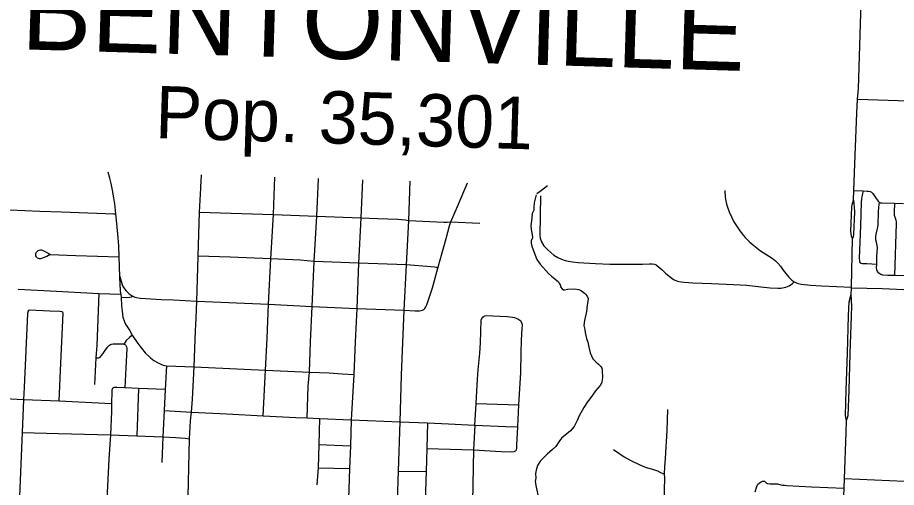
# Model space of a CAD drawing. Extents: x 653372 to 905732, y 627442 to 787275.
# Drawn here: x 659009 to 666097, y 749842 to 753633 of the extents above; entities that cross this region are included whole.
import ezdxf

# ---------------------------------------------------------------- set-up
doc = ezdxf.new("R2010")
doc.units = 0
for name, color, linetype in [('33', 7, 'Continuous'), ('34', 7, 'Continuous'), ('35', 7, 'Continuous'), ('6', 7, 'Continuous')]:
    doc.layers.add(name, color=color, linetype=linetype)

msp = doc.modelspace()

# ---------------------------------------------------------------- linework, layer by layer
at = {"layer": '33'}
for points in [[(665750.6, 752158.5), (665753.4, 752237.5), (665765.4, 752523.4), (665776.4, 752861.8), (665784.2, 752975.8), (665790.1, 753059), (665809.2, 753667.6), (665821.4, 753986.1), (665822.6, 754011), (665827.6, 754110), (665837.6, 754326.1), (665845.5, 754476.3), (665857.3, 754725.5), (665870.8, 755060.3), (665875.3, 755151.5), (665889.4, 755308.4), (665902.2, 755504.9), (665923, 756054.4), (665953, 756658.5), (665962.3, 756805.9), (665967.2, 756905.6), (665969, 756942), (665972.3, 757010.8)], [(665784.2, 752975.8), (666604.8, 752948.1)], [(659841.5, 751402.3), (659836.4, 751474.9), (659832.3, 751543), (659828.2, 751703.3), (659824.2, 751792.6), (659819.4, 751855.2), (659808.5, 751972.8), (659800.2, 752050.5), (659792, 752130.5), (659785.1, 752178.6), (659774.7, 752240.2), (659764.1, 752294), (659753.7, 752337.3), (659739.1, 752385.9)], [(660433.3, 750816.3), (660438.3, 750963.7), (660443.8, 751105.4), (660448.1, 751206.8), (660453.3, 751345.4), (660460, 751521.8), (660464.4, 751708.4), (660475.1, 752063.9), (660485.8, 752257.1), (660489.6, 752322.7), (660491.2, 752351.6), (660491, 752363.3)], [(660989.1, 750420.2), (661008.7, 750787.3), (661021.1, 751046.1), (661033.3, 751320.2), (661051.6, 751686.4), (661071.6, 752044.4), (661084.3, 752345.5)], [(661344.1, 750402.3), (661352.6, 750659.3), (661362.5, 750773.2), (661370.6, 751016.3), (661385.3, 751301.8), (661402.2, 751666.1), (661422.1, 752029.5), (661435.4, 752330.7), (661435.6, 752334.9)], [(661791.6, 752324.2), (661776.9, 752016.2)], [(662051.6, 749054.1), (662057.6, 749373.6), (662064.6, 749504.9), (662070.7, 749595.4), (662074.8, 749814.9), (662080.9, 749974.3), (662093.6, 750371.3), (662106.3, 750747.6), (662116.4, 751010.5), (662127.9, 751272.1), (662145.5, 751637.9), (662164.3, 751997), (662174.6, 752312.7)], [(662127.9, 751272.1), (662214.3, 751267.1), (662249.8, 751267), (662264.2, 751269), (662274.2, 751272.2), (662285.2, 751278.8), (662292.8, 751286.9), (662301.6, 751299), (662310.5, 751315.5), (662354.5, 751451.8), (662397.3, 751612.4), (662464.6, 751849.6), (662492.8, 751953.8), (662503, 751984.3), (662557.6, 752107.5), (662637.6, 752298.8)], [(665753.4, 752237.5), (665828.4, 752234.1), (665861.3, 752233.1), (665870.8, 752231.7), (665884.7, 752228.5), (665896.8, 752223.1), (665907.7, 752213.8), (665933.9, 752174.4), (665949.4, 752150.5), (665959.2, 752141.8), (665965.3, 752138.8), (665979.2, 752137.9), (666080.9, 752135.4), (666154, 752133.2)], [(665828.4, 752234.1), (665822.1, 752212.5), (665816.9, 752188), (665815.2, 752171.3), (665813.8, 752141.2), (665807.1, 751956.3), (665797.4, 751689.7), (665798.1, 751674), (665799.4, 751661.7), (665804.2, 751654.2), (665810.2, 751650.7), (665820.2, 751648.7), (665859.3, 751647.6), (665938, 751644.3)], [(658461, 752105.2), (658630.8, 752096.9), (658719, 752093), (658946, 752082.2), (659187.6, 752071.7), (659363.4, 752065.7), (659718.3, 752051.8), (659781.9, 752049.9), (659800.2, 752050.5)], [(665742.6, 751851.8), (665735.5, 751869.4), (665731.1, 751894.4), (665730.1, 751906.1), (665737, 752105.6), (665740.1, 752122.7), (665750.6, 752158.5)], [(665750.6, 752158.5), (665753.2, 752130.6), (665756.7, 752103.8), (665759, 752066.8), (665751.7, 751882.2), (665748.1, 751862.6), (665742.6, 751851.8)], [(666223.1, 751548.5), (666081.2, 751551.6), (666028.1, 751552.7), (665986.8, 751554.5), (665971.3, 751559.4), (665954.3, 751570), (665944.1, 751585.4), (665938.3, 751597.9), (665936, 751613), (665938, 751644.3), (665939.9, 751706.3), (665943.7, 751776.1), (665941.5, 751795.1), (665935.5, 751821), (665930.5, 751840.8), (665929.9, 751857), (665930.9, 751870.2), (665936.7, 751895.8), (665942.4, 751920.8), (665948.1, 751941.3), (665948.7, 751960.9), (665952.3, 752063.4), (665954.1, 752104.1), (665957.5, 752124.7), (665959.2, 752141.8)], [(666080.9, 752135.4), (666078.6, 752062.4), (666079.6, 752039.4), (666085.7, 752018), (666092.9, 751997.1), (666094.8, 751986.4), (666094.9, 751971.3), (666081.2, 751551.6)], [(660475.1, 752063.9), (661071.6, 752044.4), (661422.1, 752029.5), (661776.9, 752016.2), (661914.8, 752011.3), (662074.9, 752005.5), (662135.7, 752000.7), (662164.3, 751997), (662446.2, 751983), (662474.8, 751983.6), (662503, 751984.3), (662736.4, 751973.4)], [(661776.9, 752016.2), (661759, 751650.4), (661744.7, 751285.7), (661731.1, 751017.8), (661719.8, 750752.1), (661699.9, 750386.5), (661692.7, 750178.4), (661685.1, 749994.1), (661674.2, 749669.3)], [(665731.4, 751401.5), (665733.8, 751450.4), (665733.9, 751459), (665742.6, 751851.8)], [(659272.1, 751721.8), (659243.7, 751705.7), (659208.2, 751691.5), (659195.1, 751687.7), (659185.5, 751687.4), (659177.7, 751689.3), (659170.9, 751692), (659163.9, 751696.8), (659160.5, 751701.7), (659156.2, 751711.6), (659154.9, 751722.1), (659156.8, 751730.1), (659159.9, 751736.8), (659166.7, 751746.4), (659175.7, 751752.6), (659183.6, 751756.3), (659193, 751758.3), (659202.1, 751757.7), (659213.4, 751754.4), (659227.2, 751748.1), (659246, 751736.9), (659259.7, 751728.7), (659272.1, 751721.8)], [(659272.1, 751721.8), (659477.8, 751714.3), (659828.2, 751703.3)], [(662397.3, 751612.4), (662386.6, 751615.7), (662372.9, 751619.1), (662341.9, 751622.5), (662145.5, 751637.9), (661759, 751650.4), (661402.2, 751666.1), (661288.2, 751675.3), (661051.6, 751686.4), (660722.2, 751700.7), (660464.4, 751708.4)], [(659832.3, 751543), (659856.2, 751468.8), (659870.6, 751444.9), (659885.1, 751427), (659908.5, 751405.2), (659925.6, 751393.2), (659937.9, 751385.4), (659953.5, 751377.3), (659969, 751373.2), (659998.4, 751369.3), (660043.5, 751366.8), (660166.1, 751359.5), (660265.9, 751354.3), (660453.3, 751345.4), (661033.3, 751320.2), (661385.3, 751301.8), (661744.7, 751285.7), (662127.9, 751272.1)], [(665271.4, 751501.3), (665303.3, 751487), (665327.7, 751480.7), (665404.2, 751474.5), (665491.4, 751469.6), (665733.9, 751459)], [(659013, 751440.7), (659321.8, 751425.9), (659664.6, 751405.6), (659841.5, 751402.3)], [(659664.6, 751405.6), (659647.7, 750990.7), (659640.1, 750887.6), (659629.7, 750671.7)], [(659841.5, 751402.3), (659843.5, 751376), (659846.6, 751306.6), (659852, 751263.6), (659858.9, 751217.1), (659871.1, 751178.3), (659879.5, 751158.5), (659889.1, 751144.3), (659910.4, 751111.7), (659932.5, 751069.2), (659980.1, 751003.7), (660039.1, 750927.8), (660081.4, 750888.6), (660107, 750867.2), (660136.5, 750849.6), (660163.4, 750836), (660183.4, 750827.2), (660209.6, 750822.5), (660433.3, 750816.3), (661008.7, 750787.3), (661362.5, 750773.2), (661522.5, 750765.9), (661625.9, 750759.2), (661719.8, 750752.1)], [(665693.7, 750381), (665684.9, 750422.8), (665691.6, 750627.8), (665701.1, 750924.5), (665710.2, 751227.8), (665715.4, 751339.6), (665731.4, 751401.5)], [(665693.7, 750381), (665708, 750422), (665714.7, 750627.1), (665724.2, 750923.8), (665733.3, 751226.9), (665736.7, 751301.4), (665731.4, 751401.5)], [(666214.6, 751433.7), (665983, 751445.1), (665733.8, 751450.4)], [(659843.5, 751376), (659886.9, 751375.3), (659914.2, 751376.1), (659926.4, 751380), (659937.9, 751385.4)], [(659345.2, 750540.6), (659357.7, 750843.4), (659376.7, 751246.8), (659373.6, 751254.2), (659365.4, 751258.9), (659348.5, 751260.6), (659268.9, 751265.2), (659105, 751271.2), (659096, 751268.7), (659091.8, 751260.4), (659091, 751252.1), (659089.7, 751244.4), (659061.2, 750649.5), (659057.7, 750550.3), (659046.7, 750285), (659021.8, 749707.4)], [(662310.1, 750155.8), (662687, 750145.5), (662909.8, 750133.2), (662990.1, 750130.2), (663015.1, 750131.9), (663025.3, 750138.5), (663033, 750146.4), (663034.5, 750155.7), (663036, 750183.7), (663042.2, 750330.8), (663052.5, 750507.3), (663067.9, 750769.7), (663069.5, 750927.6), (663073.2, 751030.4), (663079.2, 751123.7), (663081.2, 751151.1), (663077.9, 751164.9), (663068.9, 751182.8), (663042.2, 751200.9), (663031.7, 751205.6), (663020, 751210.3), (663000.8, 751214), (662957.3, 751219.1), (662782, 751225.7), (662771.1, 751224.6)], [(662696.9, 750344.2), (662706.4, 750518), (662717.5, 750715.2), (662723.4, 750791.2), (662732, 750871.9), (662737.8, 750925.6), (662741.8, 751009), (662748.9, 751191.4), (662752.4, 751205.3), (662760, 751216.5), (662771.1, 751224.6)], [(659932.5, 751069.2), (659911, 751050.7), (659885.3, 751026.2), (659875.9, 751014), (659866.3, 750999)], [(659640.1, 750887.6), (659655.1, 750887.2), (659664.6, 750888.5), (659676, 750894.3), (659688.7, 750909.6), (659734.6, 750973.4), (659749.6, 750989.1), (659757.6, 750995), (659766.6, 750999.2), (659780, 751001.6), (659857.5, 751000.9), (659866.3, 750999), (659878.4, 750992.5), (659883.2, 750987.3), (659888.5, 750977.1), (659889.2, 750963.7), (659881.1, 750805.7), (659873.5, 750645.1)], [(660209.6, 750822.5), (660199.1, 750632.5), (660191.1, 750463.2), (660181.7, 750249.8)], [(660381, 749421.4), (660382.5, 749653.8), (660394.9, 750233.4), (660403.4, 750379.9), (660411.1, 750449), (660419.1, 750552.9), (660433.3, 750816.3)], [(660199.1, 750632.5), (659984.2, 750639.8), (659873.5, 750645.1), (659808.2, 750649.3), (659789.2, 750648.1), (659781.3, 750645), (659775.6, 750641.3), (659772.1, 750635.8), (659769.6, 750627), (659768.1, 750614.8), (659765.8, 750517.9), (659767.6, 750484.7), (659767.2, 750454.3), (659758.2, 750265.3), (659744.4, 750070.5), (659731.8, 749798.3), (659726.9, 749677.9)], [(659984.2, 750639.8), (659971.1, 750257.3)], [(658400.9, 750586.8), (658595.6, 750576.5), (658751.8, 750566.8), (659057.7, 750550.3), (659345.2, 750540.6), (659765.8, 750517.9)], [(662706.4, 750518), (663052.5, 750507.3)], [(664195.5, 749149.8), (664224.5, 749532.3), (664224.4, 749563.1), (664225.3, 749707.6), (664226.1, 749825.8), (664228, 749913.5), (664226.5, 749953.7), (664229.5, 750007.5), (664235.7, 750076.6), (664248, 750301), (664252.4, 750471.6)], [(660191.1, 750463.2), (660411.1, 750449), (660697.5, 750435), (660989.1, 750420.2), (661252.7, 750407.5), (661344.1, 750402.3), (661444.6, 750398.1), (661699.9, 750386.5), (662093.6, 750371.3), (662314.5, 750363.4), (662484.5, 750356), (662696.9, 750344.2), (662946.5, 750333.1), (663042.2, 750330.8)], [(661444.6, 750398.1), (661438.3, 750189.3), (661433.3, 750000.9), (661423.1, 749863.9)], [(662314.5, 750363.4), (662310.1, 750155.8), (662303.9, 749970.1), (662299.2, 749811.9), (662296.9, 749591.8)], [(662696.9, 750344.2), (662687, 750145.5), (662675.8, 749587.4)], [(665670.2, 749026.3), (665670.6, 749055.7), (665673.6, 749102), (665679.8, 749167.7), (665681.7, 749212.6), (665681.1, 749251.2), (665676.5, 749296.4), (665669.3, 749372.7), (665665, 749426.8), (665662.2, 749468.8), (665661.9, 749521.1), (665663.3, 749585.7), (665675, 749836.9), (665677.3, 749913.9), (665692, 750286.2), (665693.7, 750381)], [(659046.7, 750285), (659340.1, 750277.3), (659758.2, 750265.3), (659971.1, 750257.3), (660181.7, 750249.8), (660285.6, 750246.1), (660323.4, 750243.3), (660360.6, 750240.5), (660394.9, 750233.4)], [(660181.7, 750249.8), (660172.6, 750043.1)], [(661438.3, 750189.3), (661692.7, 750178.4)], [(663816.2, 750147.2), (663902.3, 750089.3), (663955.2, 750058.6), (664027.5, 750025.4), (664077.3, 750003.1), (664130.8, 749988.4), (664169.8, 749975.5), (664194.9, 749961.6), (664212.7, 749954.1), (664226.5, 749953.7)], [(661433.3, 750000.9), (661685.1, 749994.1)], [(662080.9, 749974.3), (662303.9, 749970.1)], [(665677.3, 749913.9), (666161.2, 749892.5), (666852.7, 749863.4)], [(664958.7, 749806.2), (664970.1, 749850.6), (664979.1, 749868.8), (664988.8, 749877.4), (665005.9, 749888.1), (665017.2, 749892.2), (665023.9, 749892.6), (665032.2, 749891.2), (665041, 749885.4), (665049.7, 749876.7), (665056.8, 749873.1), (665075.2, 749870.9), (665107.7, 749872.2), (665123.9, 749871.7), (665136.7, 749870.8), (665163.8, 749863.8), (665178.8, 749860.5), (665193, 749859), (665212.3, 749857.3), (665411.7, 749846.9), (665675, 749836.9)]]:
    msp.add_lwpolyline(points, dxfattribs=at)
at = {"layer": '34'}
for points in [[(663226.4, 752194.3), (663221.6, 751875.8), (663224.5, 751852.6), (663233.2, 751824.4), (663253, 751792.3), (663285.3, 751758), (663333.3, 751716.1), (663367.2, 751696.7), (663394.7, 751682.8), (663425.3, 751671.8), (663453.1, 751666.8), (663485, 751662.2), (663531.2, 751657.3), (663669.5, 751649.6), (663784.9, 751644.3), (663971.4, 751642.9), (664048.5, 751643.5), (664106.2, 751644.8), (664127.6, 751645.3), (664144.7, 751642.4), (664158.2, 751637.3), (664176.3, 751624.3), (664206.4, 751599), (664235.2, 751569.6), (664264.2, 751545.5), (664285.8, 751530.6), (664305.3, 751517.2), (664330.6, 751506.9), (664360.7, 751501.2), (664385.5, 751496.9), (664455, 751493.1), (664605.1, 751487.4), (664782.1, 751479.7), (664889.5, 751473.5), (665004.4, 751461.7), (665079.7, 751453.5), (665140.8, 751449.9), (665164.9, 751450.9), (665204.9, 751458.1), (665232.5, 751468.5), (665258, 751486.8), (665271.4, 751501.3)], [(664711.8, 752236.5), (664712.5, 752231.3), (664715.2, 752187.5), (664721.5, 752154.8), (664726.8, 752126.7), (664735, 752102.1), (664747.3, 752066.5), (664766.8, 752025.6), (664786.3, 751985.8), (664806.6, 751952.2), (664827.4, 751919.1), (664849, 751891.5), (664877.9, 751857.4), (664915.4, 751819.9), (664945.5, 751794.3), (664973.9, 751771.6), (665000.7, 751751.8), (665043.6, 751725.3), (665094.7, 751692.4), (665120.9, 751671.5), (665140.5, 751652.4), (665162.1, 751628.2), (665184.7, 751595.6), (665204, 751568.2), (665229.3, 751538.5), (665254.3, 751513.7), (665271.4, 751501.3)]]:
    msp.add_lwpolyline(points, dxfattribs=at)
at = {"layer": '35'}
for points in [[(663197.7, 752212.3), (663223.3, 752232.9), (663282.9, 752278.7), (663283.7, 752279.4)], [(663191, 752202), (663175.7, 752138.6), (663173.4, 752099.5), (663172.8, 752079.4), (663158.5, 752051.8), (663156.3, 752017.1), (663147.7, 751951.3), (663153.2, 751910.8), (663160.1, 751880.4), (663160.5, 751856.9), (663150.8, 751831.4), (663151.3, 751812.3), (663156.2, 751789.8), (663176, 751738.8), (663197.8, 751681), (663222.4, 751644.5), (663290.7, 751568.5), (663314.6, 751546.5), (663342, 751524.4), (663370.4, 751501.1), (663379.9, 751484.1), (663387.4, 751470.4), (663388.2, 751461.4), (663401.1, 751443.1), (663411, 751437.2), (663421, 751435.8), (663444.7, 751440.7), (663500.8, 751445.7), (663535.4, 751440.2), (663557.4, 751427.2), (663580.3, 751409.7), (663589.1, 751401.9), (663602, 751384.7), (663610.4, 751366.6), (663608.6, 751343.1), (663603.2, 751313), (663596, 751261.7), (663580.4, 751189.4), (663575.8, 751147.2), (663582.7, 751116.7), (663587.6, 751092), (663598.5, 751043.5), (663607.7, 751015.2), (663615.3, 750972.4), (663627.5, 750928), (663636.8, 750903.1), (663649.5, 750880.3), (663675.5, 750851.5), (663695.2, 750835.3), (663713.7, 750817.9), (663721.1, 750803.1), (663722.8, 750784.1), (663726.8, 750731.3), (663721, 750687.8), (663708, 750664.7), (663689.4, 750642.8), (663670.9, 750621), (663639.4, 750579.4), (663605.5, 750533.3), (663576.1, 750486.1), (663537.2, 750420), (663522.6, 750382.4), (663511.9, 750361.4), (663497.6, 750332.8), (663467.5, 750298.9)], [(663467.5, 750298.9), (663394.5, 750240.2), (663374.4, 750208.8), (663350.2, 750172.3), (663322.5, 750147.5), (663279.1, 750110.3), (663227.4, 750055.4), (663203.3, 750020.2), (663190.6, 749982.1), (663186.5, 749954.6), (663187.4, 749917.4), (663184.6, 749888.6), (663191.5, 749842.9), (663209.5, 749759.1), (663214.1, 749740.9), (663221.8, 749719.5), (663252.1, 749682.6), (663258.5, 749661.5), (663259.8, 749638.8), (663257.8, 749573.4)]]:
    msp.add_lwpolyline(points, dxfattribs=at)

# ---------------------------------------------------------------- texts
at = {"layer": '6'}
for s, height, p in [('BENTONVILLE', 633.599, (659033.5, 753377.3)), ('Pop. 35,301', 422.399, (660114.8, 752660.6))]:
    msp.add_text(s, height=height, rotation=358.28003, dxfattribs=at).set_placement(p)

doc.saveas('drawing.dxf')
